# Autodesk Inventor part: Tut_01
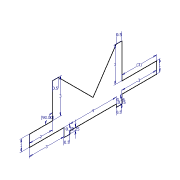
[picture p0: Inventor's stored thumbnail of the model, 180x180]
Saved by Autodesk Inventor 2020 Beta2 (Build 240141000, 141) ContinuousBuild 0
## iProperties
Created: 2019-02
Part Number: Tut_01
Material: Generic
Document SubType Name: Modeling
Designer: LENOVO-CADCIM
Density: 1 g/cm^3
Appearance: Default
Author: LENOVO-CADCIM
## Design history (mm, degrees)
sketch "Sketch1"
  geometry: L1 (0, 0)-(3, 3); L2 (3, 3)-(3, 3.5); L3 (3, 3.5)-(0, 3.5); L4 (0, 3.5)-(0, 5.5); L5 (0, 5.5)-(-1, 5.5); L6 (-1, 5.5)-(-1, 2.5); L7 (-1, 2.5)-(-1.75, 2.5); L8 (-1.75, 2.5)-(-1.75, 2); L9 (-1.75, 2)-(-1.5, 2); L10 (-1.5, 2)-(-1.5, -2); L11 (-1.5, -2)-(-1.75, -2); L12 (-1.75, -2)-(-1.75, -2.5); L13 (-1.75, -2.5)-(-1.01, -2.5); L14 (-1.01, -2.5)-(-1.01, -5.5); L15 (-1.01, -5.5)-(-0.01, -5.5); L16 (-0.01, -5.5)-(-0.01, -2.5); L17 (-0.01, -2.5)-(2.99, -2.5); L18 (2.99, -2.5)-(2.99, -2); L19 (2.99, -2)-(0, 0)
  constraints: 38 end point, 10 perpendicular, 3 point on line, 2 horizontal, 2 vertical
  dimensions: "d0" = 0.5 distance of L1.end L2.end; "d1" = 3 distance of L2.end L3.end; "d2" = 2 distance of L3.end L4.end; "d3" = 90 deg angle of L3 L4 (derived); "d4" = 1 distance of L4.end L5.end; "d5" = 3 distance of L5.end L6.end; "d6" = 0.75 distance of L6.end L7.end; "d7" = 0.5 distance of L7.end L8.end; "d8" = 0.25 distance of L8.end L9.end; "d9" = 4 distance of L9.end L10.end; "d10" = 0.25 distance of L10.end L11.end; "d11" = 0.5 distance of L11.end L12.end; "d12" = 0.74 distance of L12.end L13.end; "d13" = 3 distance of L13.end L14.end; "d14" = 1 distance of L14.end L15.end; "d15" = 3 distance of L15.end L16.end (derived); "d16" = 3 distance of L16.end L17.end; "d17" = 0.5 distance of L17.end L18.end
